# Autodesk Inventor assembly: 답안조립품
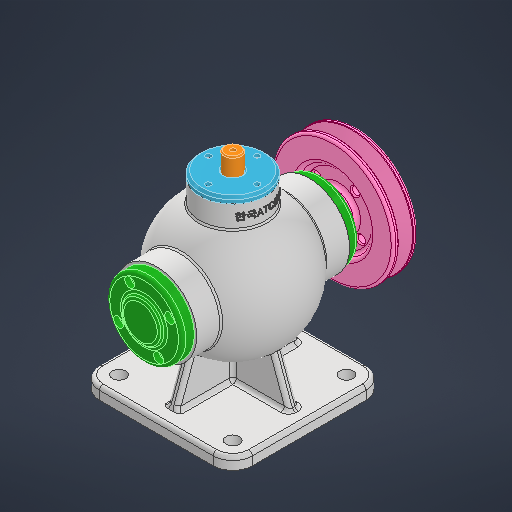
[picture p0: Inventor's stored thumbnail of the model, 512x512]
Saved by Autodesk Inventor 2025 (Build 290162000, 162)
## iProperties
Created: 2025-08
Part Number: 답안조립품
Document SubType Name: Assembly
Designer: infra023
Author: infra023
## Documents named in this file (15)
- C:\Users\infra023\Desktop\750807V1002\답안조립품.iam
- C:\Users\infra023\Desktop\750807V1002\본체.ipt
- C:\Users\infra023\Desktop\750807V1002\V-벨트풀리\V-벨트풀리.ipt
- C:\Users\infra023\Desktop\750807V1002\너트 M8\너트 M8.ipt
- C:\Users\infra023\Desktop\750807V1002\뒤커버\뒤커버.ipt
- C:\Users\infra023\Desktop\750807V1002\베어링- 6202\베어링- 6202.ipt
- C:\Users\infra023\Desktop\750807V1002\볼트 M4 x 12\볼트 M4 x 12.ipt
- C:\Users\infra023\Desktop\750807V1002\볼트 M4 x 16\볼트 M4 x 16.ipt
- C:\Users\infra023\Desktop\750807V1002\상부커버\상부커버.ipt
- C:\Users\infra023\Desktop\750807V1002\슬라이드\슬라이드.ipt
- C:\Users\infra023\Desktop\750807V1002\앞커버\앞커버.ipt
- C:\Users\infra023\Desktop\750807V1002\오일실 15 30 7\오일실 15 30 7.ipt
- C:\Users\infra023\Desktop\750807V1002\칼라\칼라.ipt
- C:\Users\infra023\Desktop\750807V1002\키 4 x 4 x 12\키 4 x 4 x 12.ipt
- C:\Users\infra023\Desktop\750807V1002\편심축\편심축.ipt
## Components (1 placed, 1 different names)
1. V-벨트풀리:1
